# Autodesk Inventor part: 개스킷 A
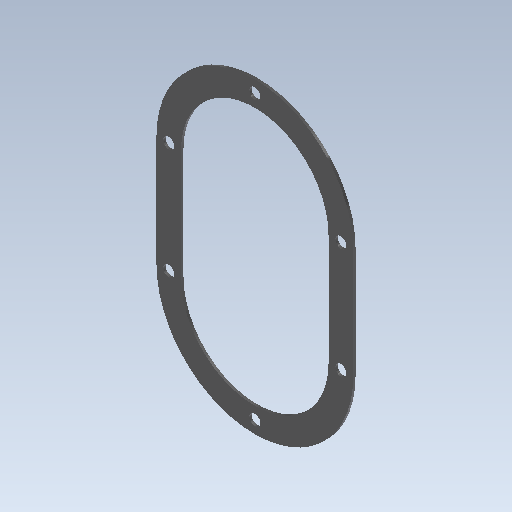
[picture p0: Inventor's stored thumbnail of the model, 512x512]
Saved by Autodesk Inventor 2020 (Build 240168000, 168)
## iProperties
Created: 2020-04
Part Number: 개스킷 A
Material: 고무
Document SubType Name: Modeling
Designer: mduedu
Density: 0.93 g/cm^3
Mass: 2.61813 g
Surface Area: 62.9733 cm^2
Volume: 2.81519 cm^3
Appearance: 고무 - 검은색 - 버전 1.1
Author: mduedu
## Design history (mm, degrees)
sketch "스케치1"
  geometry: L1 (-40, 0)-(-40, -45); L2 (40, 0)-(40, -45); A1 r 40 centre (0, 0) between (40, 0) and (-40, 0); A2 r 40 centre (0, -45) between (-40, -45) and (40, -45); 1 further point
  constraints: 4 end point, 4 point on circle, 4 tangent, 2 centre point, 1 coincident, 1 equal radius, 1 vertical alignment
  dimensions: "d0" = 80 diameter of A1; "d21" = 45 distance of point (0, 0) A2.centre
extrude "돌출1" new body sketch "스케치1" distance "d1" = 1; taper "d2" = 0 deg
sketch "스케치4"
  geometry: L1 (-30, 0)-(-30, -45); L2 (30, 0)-(30, -45); A1 r 30 centre (0, 0) between (30, 0) and (-30, 0); A2 r 30 centre (0, -45) between (-30, -45) and (30, -45); 1 further point
  constraints: 4 end point, 4 point on circle, 4 tangent, 2 centre point, 1 coincident, 1 equal radius, 1 vertical alignment
  dimensions: "d17" = 60 diameter of A1; "d24" = 45 distance of point (0, 0) A2.centre
extrude "돌출3" cut sketch "스케치4" extent not by distance; stored distance "d18" = 1; taper "d19" = 0 deg
sketch "스케치3"
  geometry: A1 r 35 centre (0, 0) between (0, 35) and (-35, 0); A2 r 35 centre (0, -45) between (-35, -45) and (0, -80); 3 further points
  constraints: 6 point on circle, 5 vertical alignment, 3 horizontal alignment, 2 centre point, 1 coincident, 1 equal radius
  dimensions: "d6" = 70 diameter of A1; "d28" = 45 distance of point (0, 0) A2.centre
hole "구멍1" sketch "스케치3" at (0, 35), (-35, 0), (35, 0), (35, -45), (-35, -45), (0, -80) diameter "d7" = 4.5; stored, may be unused: countersink angle "d11" = 90 deg, drill point angle "d13" = 118 deg; dims "d8" = 6, "d9" = 4, "d10" = 2, "d12" = 8
node "솔리드1"
